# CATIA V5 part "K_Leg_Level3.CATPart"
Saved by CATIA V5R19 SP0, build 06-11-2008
Part number: Leg_Level3
Bounding box of the stored display mesh (mm): x -20.363 to 20.363, y 53.891 to 68.157, z -942.735 to -597.735
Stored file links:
  G:\Khaled_CFAO_2011\SIL\SIL_GR2\ctanaphiko\Khaled\CAD_ThinkMOTION\K_Leg_Level3.CATPart
  G:\Khaled_CFAO_2011\SIL\SIL_GR2\ctanaphiko\CATIA\Conception_Tripod.CATProduct
  G:\Khaled_CFAO_2011\SIL\SIL_GR2\ctanaphiko\CATIA\Squelette.CATPart
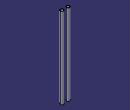
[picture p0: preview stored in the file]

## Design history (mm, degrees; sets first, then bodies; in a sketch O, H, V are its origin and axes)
External parameters (linked from other documents)
  External.Dia_Leg_Step3 = 14.3 mm
  External.Thick_Leg_Step3 = 1.43 mm
AxisSystem1: origin (0, 0, 0), X (1, 0, 0), Y (0, 1, 0), Z (0, 0, 1)
Set1
  Plane1: linked copy from another document
  DatumPoint1: linked copy from another document
  DatumPoint2: linked copy from another document
  Line1: linked copy from another document
Body1 (main body)
  Sketch1 on Plane1, origin (0, 0, -597.7345), H (1, 0, 0), V (0, 1, 0)
    circle A1 centre (-13.2127, 61.024) radius 7.15
    point P1 (-13.2127, 61.024)
    circle A2 centre (13.2127, 61.024) radius 7.15
    point P2 (13.2127, 61.024)
    reference projected point E1 (-13.2127, 61.024) from DatumPoint1
    reference projected point E2 (13.2127, 61.024) from DatumPoint2
    radius A1 = 7.15 {= External.Dia_Leg_Step3 /2}
    radius A2 = 7.15 {= External.Dia_Leg_Step3 /2}
    coincidence: P1 E1, P2 E2
  Rib1: profile Sketch1, centre curve Line1, thin wall 1.43 {= External.Thick_Leg_Step3}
